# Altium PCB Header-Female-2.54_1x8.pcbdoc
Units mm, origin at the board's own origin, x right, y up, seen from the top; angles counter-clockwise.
Board outline 33.52 x 15.16 mm, 2 copper layers (Top Layer, Bottom Layer), stack 0 mm thick; 1 components, 0 nets, 8 pads, 0 vias.
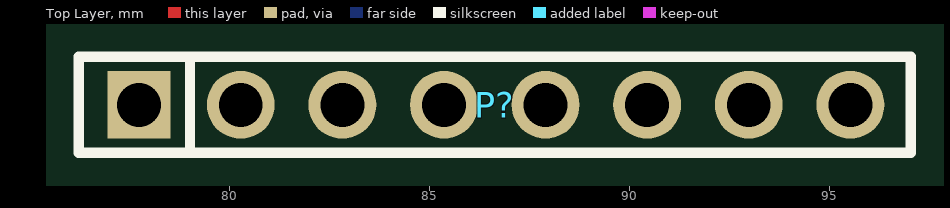
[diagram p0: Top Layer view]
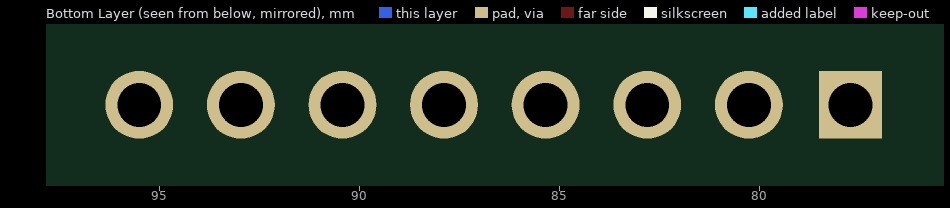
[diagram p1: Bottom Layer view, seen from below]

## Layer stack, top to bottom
Top Layer: signal copper (thickness not stored)
Bottom Layer: signal copper (thickness not stored)

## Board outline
103.37,69.85 69.85,69.85 69.85,85.009 103.37,85.009

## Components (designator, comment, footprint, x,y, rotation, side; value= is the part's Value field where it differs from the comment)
P? "2.54-1*8P母环保" HDR-TH_8P-P2.54-V-F 86.619,77.46 r0 top

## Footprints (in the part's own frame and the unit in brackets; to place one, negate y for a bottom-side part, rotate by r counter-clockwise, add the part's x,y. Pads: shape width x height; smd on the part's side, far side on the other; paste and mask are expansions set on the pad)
HDR-TH_8P-P2.54-V-F [mil]
  rect 62x66.9 hole 43.3: 1(-350,0)
  round 66.9 hole 43.3: 2(-250,0) 3(-150,0) 4(-50,0) 5(50,0) 6(150,0) 7(250,0) 8(350,0)
  silkscreen extent -409,-47 410,47

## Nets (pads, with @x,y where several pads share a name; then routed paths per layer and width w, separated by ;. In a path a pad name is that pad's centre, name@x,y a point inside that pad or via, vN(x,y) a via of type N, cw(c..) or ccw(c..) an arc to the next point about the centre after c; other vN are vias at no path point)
pads on no net: P?.1 P?.2 P?.3 P?.4 P?.5 P?.6 P?.7 P?.8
